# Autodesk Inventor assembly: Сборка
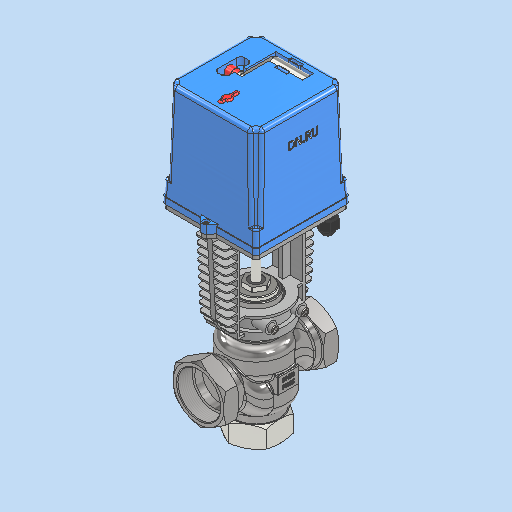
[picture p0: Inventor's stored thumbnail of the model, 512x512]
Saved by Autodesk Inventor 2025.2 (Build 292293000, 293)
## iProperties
Created: 2026-04
Part Number: Сборка
Document SubType Name: Assembly
Designer: igorr
Author: igorr
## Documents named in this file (7)
- D:\PROJECT CAD\DN.RU\...197(ACTUALE). VRg3M-S-31M-PED-T Клапан регулирующий трехходовой DN.ru\Исходники\DN50\Сборка.iam
- D:\PROJECT CAD\DN.RU\...197(ACTUALE). VRg3M-S-31M-PED-T Клапан регулирующий трехходовой DN.ru\Исходники\DN50\Деталь 1.ipt
- D:\PROJECT CAD\DN.RU\...197(ACTUALE). VRg3M-S-31M-PED-T Клапан регулирующий трехходовой DN.ru\Исходники\DN50\Деталь 2.ipt
- D:\PROJECT CAD\DN.RU\...197(ACTUALE). VRg3M-S-31M-PED-T Клапан регулирующий трехходовой DN.ru\Исходники\DN50\Деталь 3.ipt
- C:\Users\igorr\OneDrive\Документы\Inventor\Content Center Files\R2025\ru-RU\AS 1421(2)\AS 1421 - M10 x 12 засверленный конец.ipt
- C:\Users\igorr\OneDrive\Документы\Inventor\Content Center Files\R2025\ru-RU\AS 1420\AS 1420 - 1973 - M5 x 10.ipt
- C:\Users\igorr\OneDrive\Документы\Inventor\Content Center Files\R2025\ru-RU\AS 1427(05)\AS 1427 - M3 x 8(5) II.ipt
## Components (9 placed, 6 different names)
1. Деталь 1:1 — Касательность:1, Касательность:2, Угол:1, Совмещение:1, Совмещение:5, Угол:3, Совмещение:8, Совмещение:10, Совмещение:11
2. Деталь 2:1 — Касательность:1, Касательность:2, Угол:1, Совмещение:1
3. Деталь 3:1 — Совмещение:2, Совмещение:3, Угол:2, Совмещение:5, Угол:3, Совмещение:11
4. AS 1420 - метрическая M5 x 10:1 — Совмещение:8
5. AS 1420 - метрическая M5 x 10:2 — Совмещение:10
6. AS 1427 H - метрическая M3 x 8:1
7. AS 1427 H - метрическая M3 x 8:2
8. AS 1421 засверленный конец - метрическая M10 x 12 засверленный конец:1 — Заподлицо:1
9. AS 1421 засверленный конец - метрическая M10 x 12 засверленный конец:2 — Заподлицо:1
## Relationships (13: Mate 7, Angle 3, Tangent 2, Flush 1)
- Касательность:1 [Tangent]: Деталь 1:1 ↔ Деталь 2:1
- Касательность:2 [Tangent]: Деталь 1:1 ↔ Деталь 2:1
- Угол:1 [Angle]: Деталь 1:1 ↔ Деталь 2:1
- Совмещение:1 [Mate]: Деталь 1:1 ↔ Деталь 2:1
- Совмещение:2 [Mate]: Деталь 3:1
- Совмещение:3 [Mate]: Деталь 3:1
- Угол:2 [Angle]: Деталь 3:1
- Совмещение:5 [Mate]: Деталь 1:1 ↔ Деталь 3:1
- Угол:3 [Angle]: Деталь 1:1 ↔ Деталь 3:1
- Совмещение:8 [Mate]: Деталь 1:1 ↔ AS 1420 - метрическая M5 x 10:1
- Совмещение:10 [Mate]: Деталь 1:1 ↔ AS 1420 - метрическая M5 x 10:2
- Совмещение:11 [Mate]: Деталь 1:1 ↔ Деталь 3:1
- Заподлицо:1 [Flush]: AS 1421 засверленный конец - метрическая M10 x 12 засверленный конец:1 ↔ AS 1421 засверленный конец - метрическая M10 x 12 засверленный конец:2
